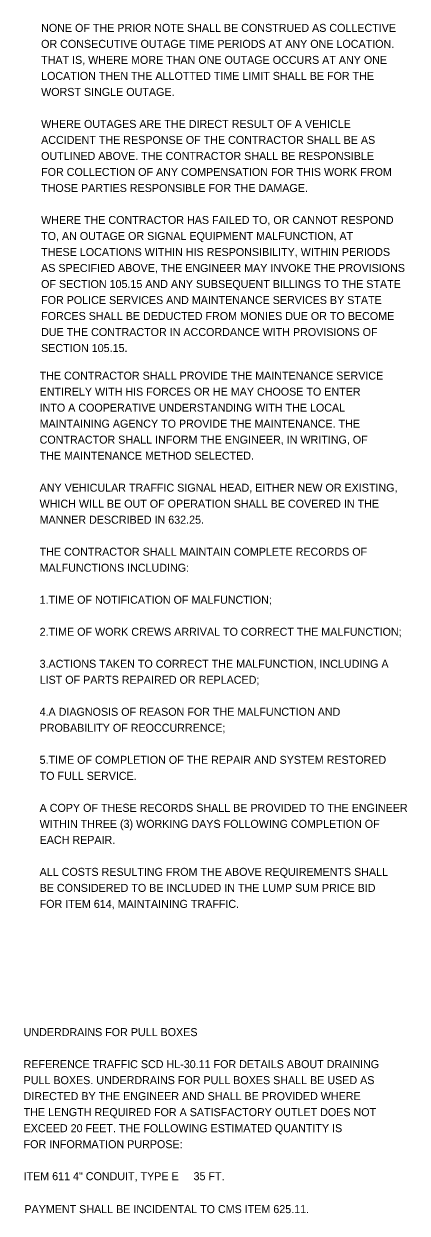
# Model space of a CAD drawing. Extents: x -11.8 to 65.2, y -26.4 to 34.6.
# Drawn here: x 37.69 to 44.38, y 3.18 to 23.99 of the extents above; entities that cross this region are included whole.
import ezdxf

# ---------------------------------------------------------------- set-up
doc = ezdxf.new("R2010")
doc.units = 0
doc.layers.add('SH_Text', color=7, linetype='Continuous')

msp = doc.modelspace()

# ---------------------------------------------------------------- texts
at = {"layer": 'SH_Text'}
for s, p in [('NONE OF THE PRIOR NOTE SHALL BE CONSTRUED AS COLLECTIVE ', (37.989, 23.845)), ('OR CONSECUTIVE OUTAGE TIME PERIODS AT ANY ONE LOCATION. ', (37.989, 23.565)), ('THAT IS, WHERE MORE THAN ONE OUTAGE OCCURS AT ANY ONE ', (37.989, 23.285)), ('LOCATION THEN THE ALLOTTED TIME LIMIT SHALL BE FOR THE ', (37.989, 23.005)), ('WORST SINGLE OUTAGE.', (37.989, 22.725)), ('WHERE OUTAGES ARE THE DIRECT RESULT OF A VEHICLE ', (37.989, 22.165)), ('ACCIDENT THE RESPONSE OF THE CONTRACTOR SHALL BE AS ', (37.989, 21.885)), ('OUTLINED ABOVE. THE CONTRACTOR SHALL BE RESPONSIBLE ', (37.989, 21.605)), ('FOR COLLECTION OF ANY COMPENSATION FOR THIS WORK FROM ', (37.989, 21.325)), ('THOSE PARTIES RESPONSIBLE FOR THE DAMAGE.', (37.989, 21.045)), ('WHERE THE CONTRACTOR HAS FAILED TO, OR CANNOT RESPOND ', (37.989, 20.485)), ('TO, AN OUTAGE OR SIGNAL EQUIPMENT MALFUNCTION, AT ', (37.989, 20.205)), ('THESE LOCATIONS WITHIN HIS RESPONSIBILITY, WITHIN PERIODS ', (37.989, 19.925)), ('AS SPECIFIED ABOVE, THE ENGINEER MAY INVOKE THE PROVISIONS ', (37.989, 19.645)), ('OF SECTION 105.15 AND ANY SUBSEQUENT BILLINGS TO THE STATE ', (37.989, 19.365)), ('FOR POLICE SERVICES AND MAINTENANCE SERVICES BY STATE ', (37.989, 19.085)), ('FORCES SHALL BE DEDUCTED FROM MONIES DUE OR TO BECOME ', (37.989, 18.805)), ('DUE THE CONTRACTOR IN ACCORDANCE WITH PROVISIONS OF ', (37.989, 18.525)), ('SECTION 105.15.', (37.989, 18.245)), ('THE CONTRACTOR SHALL PROVIDE THE MAINTENANCE SERVICE ', (37.963, 17.762)), ('ENTIRELY WITH HIS FORCES OR HE MAY CHOOSE TO ENTER ', (37.963, 17.482)), ('INTO A COOPERATIVE UNDERSTANDING WITH THE LOCAL ', (37.963, 17.202)), ('MAINTAINING AGENCY TO PROVIDE THE MAINTENANCE. THE ', (37.963, 16.922)), ('CONTRACTOR SHALL INFORM THE ENGINEER, IN WRITING, OF ', (37.963, 16.642)), ('THE MAINTENANCE METHOD SELECTED. ', (37.963, 16.362)), ('ANY VEHICULAR TRAFFIC SIGNAL HEAD, EITHER NEW OR EXISTING, ', (37.963, 15.802)), ('WHICH WILL BE OUT OF OPERATION SHALL BE COVERED IN THE ', (37.963, 15.522)), ('MANNER DESCRIBED IN 632.25.', (37.963, 15.242)), ('THE CONTRACTOR SHALL MAINTAIN COMPLETE RECORDS OF ', (37.963, 14.682)), ('MALFUNCTIONS INCLUDING:', (37.963, 14.402)), ('1.TIME OF NOTIFICATION OF MALFUNCTION;', (37.963, 13.842)), ('2.TIME OF WORK CREWS ARRIVAL TO CORRECT THE MALFUNCTION;', (37.963, 13.282)), ('3.ACTIONS TAKEN TO CORRECT THE MALFUNCTION, INCLUDING A ', (37.963, 12.722)), ('LIST OF PARTS REPAIRED OR REPLACED;', (37.963, 12.442)), ('4.A DIAGNOSIS OF REASON FOR THE MALFUNCTION AND ', (37.963, 11.882)), ('PROBABILITY OF REOCCURRENCE;', (37.963, 11.602)), ('5.TIME OF COMPLETION OF THE REPAIR AND SYSTEM RESTORED ', (37.963, 11.042)), ('TO FULL SERVICE.', (37.963, 10.762)), ('A COPY OF THESE RECORDS SHALL BE PROVIDED TO THE ENGINEER ', (37.963, 10.202)), ('WITHIN THREE (3) WORKING DAYS FOLLOWING COMPLETION OF ', (37.963, 9.922)), ('EACH REPAIR.', (37.963, 9.642)), ('ALL COSTS RESULTING FROM THE ABOVE REQUIREMENTS SHALL ', (37.963, 9.082)), ('BE CONSIDERED TO BE INCLUDED IN THE LUMP SUM PRICE BID ', (37.963, 8.802)), ('FOR ITEM 614, MAINTAINING TRAFFIC.', (37.963, 8.522)), ('UNDERDRAINS FOR PULL BOXES', (37.683, 6.279)), ('REFERENCE TRAFFIC SCD HL-30.11 FOR DETAILS ABOUT DRAINING', (37.683, 5.719)), ('PULL BOXES. UNDERDRAINS FOR PULL BOXES SHALL BE USED AS', (37.683, 5.439)), ('DIRECTED BY THE ENGINEER AND SHALL BE PROVIDED WHERE', (37.683, 5.159)), ('THE LENGTH REQUIRED FOR A SATISFACTORY OUTLET DOES NOT', (37.683, 4.879)), ('EXCEED 20 FEET. THE FOLLOWING ESTIMATED QUANTITY IS', (37.683, 4.599)), ('FOR INFORMATION PURPOSE:', (37.683, 4.319)), ('ITEM 611 4" CONDUIT, TYPE E     35 FT.', (37.683, 3.759)), ('PAYMENT SHALL BE INCIDENTAL TO CMS ITEM 625.11.', (37.697, 3.183))]:
    msp.add_text(s, height=0.14, dxfattribs=at).set_placement(p)

doc.saveas('drawing.dxf')
